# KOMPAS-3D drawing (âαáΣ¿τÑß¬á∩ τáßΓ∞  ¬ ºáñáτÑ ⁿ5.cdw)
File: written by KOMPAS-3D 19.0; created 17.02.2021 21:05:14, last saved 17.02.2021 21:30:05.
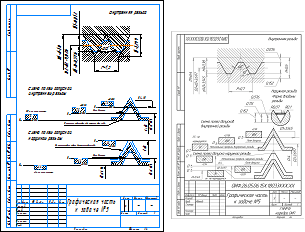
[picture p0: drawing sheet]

Sheet 1: A4, portrait

Document properties: Автор: Юрий; Полное имя файла: C:\Users\Юрий\Desktop\метрология сироп\Графическая часть  к задаче №5.cdw

Title block, sheet 1: Наименование: Графическая часть / к задаче №5; Количество листов документа: 1; Форматы листов документа: A4; Литера: у

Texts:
  Внутренняя резьба
  Схема полей допусков
  внутренней резьбы
  Поле допуска
  Номинальный профиль внутренней резьбы
  ES - не нормируется
  наружной резьбы
  ei - не нормируется
Dimensions and other numbers on the sheet: 10; 9,026; 8,376; 0,812; +0,032; +0,256; -0,236; -0,132; 1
